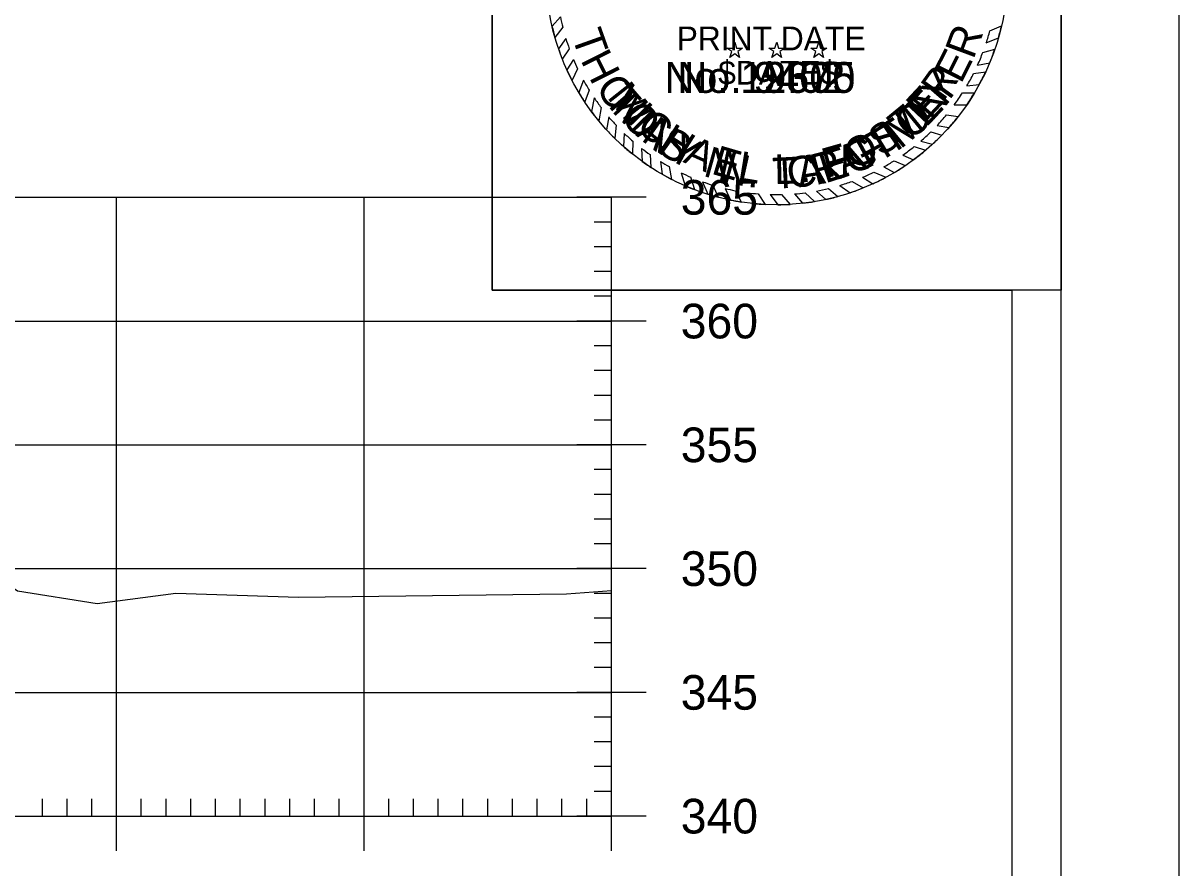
# Model space of a CAD drawing. Extents: x 1368910 to 1369601, y 380116 to 380950.
# Drawn here: x 1369553.81 to 1369600.52, y 380462.33 to 380496.46 of the extents above; entities that cross this region are included whole.
import ezdxf

# ---------------------------------------------------------------- set-up
doc = ezdxf.new("R2010")
doc.units = 0
for name, color, linetype in [('R_Axis', 7, 'Continuous'), ('R_Axis Annot', 7, 'Continuous'), ('R_Border', 7, 'Continuous'), ('R_Exist Surface', 7, 'Continuous'), ('R_Grid', 7, 'Continuous'), ('R_No Plot', 7, 'Continuous'), ('STAMP_PE_CRAFTON', 7, 'Continuous'), ('STAMP_PE_FOSTER', 7, 'Continuous'), ('STAMP_PE_SEAL-INFO', 7, 'Continuous'), ('STAMP_PE_TAEGTMEYER', 7, 'Continuous'), ('STAMP_PE_TXT', 7, 'Continuous'), ('STAMP_PRELIMINARY', 7, 'Continuous')]:
    doc.layers.add(name, color=color, linetype=linetype)

msp = doc.modelspace()

# ---------------------------------------------------------------- linework, layer by layer
at = {"layer": 'R_Axis'}
for p, q in [((1369578.99, 380489.421), (1369576.19, 380489.421)), ((1369577.59, 380464.421), (1369577.59, 380489.421)), ((1369577.59, 380488.421), (1369576.89, 380488.421)), ((1369577.59, 380487.421), (1369576.89, 380487.421)), ((1369577.59, 380486.421), (1369576.89, 380486.421)), ((1369577.59, 380485.421), (1369576.89, 380485.421)), ((1369578.99, 380484.421), (1369576.19, 380484.421)), ((1369577.59, 380483.421), (1369576.89, 380483.421)), ((1369577.59, 380482.421), (1369576.89, 380482.421)), ((1369577.59, 380481.421), (1369576.89, 380481.421)), ((1369577.59, 380480.421), (1369576.89, 380480.421)), ((1369578.99, 380479.421), (1369576.19, 380479.421)), ((1369577.59, 380478.421), (1369576.89, 380478.421)), ((1369577.59, 380477.421), (1369576.89, 380477.421)), ((1369577.59, 380476.421), (1369576.89, 380476.421)), ((1369577.59, 380475.421), (1369576.89, 380475.421)), ((1369578.99, 380474.421), (1369576.19, 380474.421)), ((1369577.59, 380473.421), (1369576.89, 380473.421)), ((1369577.59, 380472.421), (1369576.89, 380472.421)), ((1369577.59, 380471.421), (1369576.89, 380471.421)), ((1369577.59, 380470.421), (1369576.89, 380470.421)), ((1369578.99, 380469.421), (1369576.19, 380469.421)), ((1369577.59, 380468.421), (1369576.89, 380468.421)), ((1369577.59, 380467.421), (1369576.89, 380467.421)), ((1369577.59, 380466.421), (1369576.89, 380466.421)), ((1369557.59, 380463.021), (1369557.59, 380465.821)), ((1369567.59, 380463.021), (1369567.59, 380465.821)), ((1369577.59, 380463.021), (1369577.59, 380465.821)), ((1369577.59, 380465.421), (1369576.89, 380465.421)), ((1369554.59, 380464.421), (1369554.59, 380465.121)), ((1369555.59, 380464.421), (1369555.59, 380465.121)), ((1369556.59, 380464.421), (1369556.59, 380465.121)), ((1369558.59, 380464.421), (1369558.59, 380465.121)), ((1369559.59, 380464.421), (1369559.59, 380465.121)), ((1369560.59, 380464.421), (1369560.59, 380465.121)), ((1369561.59, 380464.421), (1369561.59, 380465.121)), ((1369562.59, 380464.421), (1369562.59, 380465.121)), ((1369563.59, 380464.421), (1369563.59, 380465.121)), ((1369564.59, 380464.421), (1369564.59, 380465.121)), ((1369565.59, 380464.421), (1369565.59, 380465.121)), ((1369566.59, 380464.421), (1369566.59, 380465.121)), ((1369568.59, 380464.421), (1369568.59, 380465.121)), ((1369569.59, 380464.421), (1369569.59, 380465.121)), ((1369570.59, 380464.421), (1369570.59, 380465.121)), ((1369571.59, 380464.421), (1369571.59, 380465.121)), ((1369572.59, 380464.421), (1369572.59, 380465.121)), ((1369573.59, 380464.421), (1369573.59, 380465.121)), ((1369574.59, 380464.421), (1369574.59, 380465.121)), ((1369575.59, 380464.421), (1369575.59, 380465.121)), ((1369576.59, 380464.421), (1369576.59, 380465.121)), ((1369297.59, 380464.421), (1369577.59, 380464.421)), ((1369578.99, 380464.421), (1369576.19, 380464.421))]:
    msp.add_line(p, q, dxfattribs=at)
at = {"layer": 'R_Border'}
msp.add_line((1369595.77, 380314.421), (1369595.77, 380519.881), dxfattribs=at)
at = {"layer": 'R_Exist Surface'}
msp.add_lwpolyline([(1369523.111, 380476.473), (1369549.701, 380476.252), (1369549.725, 380476.253), (1369549.738, 380476.255), (1369549.774, 380476.194), (1369553.587, 380473.527), (1369556.799, 380473.017), (1369559.991, 380473.431), (1369564.938, 380473.265), (1369575.777, 380473.406), (1369577.59, 380473.534)], dxfattribs=at)
at = {"layer": 'R_Grid'}
for p, q in [((1369297.59, 380489.421), (1369577.59, 380489.421)), ((1369557.59, 380464.421), (1369557.59, 380489.421)), ((1369567.59, 380464.421), (1369567.59, 380489.421)), ((1369577.59, 380464.421), (1369577.59, 380489.421)), ((1369297.59, 380484.421), (1369577.59, 380484.421)), ((1369297.59, 380479.421), (1369577.59, 380479.421)), ((1369297.59, 380474.421), (1369577.59, 380474.421)), ((1369297.59, 380469.421), (1369577.59, 380469.421)), ((1369297.59, 380464.421), (1369577.59, 380464.421))]:
    msp.add_line(p, q, dxfattribs=at)
at = {"layer": 'R_No Plot'}
for points in [[(1369267.182, 380523.775), (1369600.522, 380523.775), (1369600.522, 380310.438), (1369267.182, 380310.438)], [(1369593.77, 380419.151), (1369281.59, 380419.151), (1369281.59, 380517.881), (1369531.13, 380517.881), (1369531.13, 380508.001), (1369548.67, 380508.001), (1369572.77, 380508.001), (1369572.77, 380485.668), (1369593.77, 380485.668)], [(1369281.59, 380517.881), (1369531.13, 380517.881), (1369531.13, 380508.001), (1369548.67, 380508.001), (1369572.77, 380508.001), (1369572.77, 380485.668), (1369593.77, 380485.668), (1369593.77, 380316.421), (1369281.59, 380316.421)], [(1369572.77, 380510.001), (1369595.77, 380510.001), (1369595.77, 380485.668), (1369572.77, 380485.668)]]:
    msp.add_lwpolyline(points, close=True, dxfattribs=at)
at = {"layer": 'STAMP_PE_SEAL-INFO'}
for p, q in [((1369575.527, 380496.708), (1369575.188, 380496.34)), ((1369575.621, 380496.289), (1369575.308, 380495.874)), ((1369592.883, 380496.15), (1369593.355, 380496.352)), ((1369575.744, 380495.842), (1369575.45, 380495.424)), ((1369592.736, 380495.656), (1369593.227, 380495.857)), ((1369575.885, 380495.419), (1369575.604, 380495.007)), ((1369592.602, 380495.276), (1369593.084, 380495.407)), ((1369576.052, 380494.993), (1369575.79, 380494.57)), ((1369592.388, 380494.762), (1369592.876, 380494.858)), ((1369576.223, 380494.609), (1369575.996, 380494.148)), ((1369592.227, 380494.425), (1369592.715, 380494.494)), ((1369576.458, 380494.151), (1369576.267, 380493.661)), ((1369591.954, 380493.927), (1369592.455, 380493.981)), ((1369576.694, 380493.747), (1369576.51, 380493.276)), ((1369576.896, 380493.435), (1369576.787, 380492.883)), ((1369591.783, 380493.646), (1369592.26, 380493.64)), ((1369577.177, 380493.045), (1369577.075, 380492.514)), ((1369591.443, 380493.152), (1369591.948, 380493.155)), ((1369577.481, 380492.667), (1369577.394, 380492.147)), ((1369591.135, 380492.758), (1369591.597, 380492.679)), ((1369577.784, 380492.33), (1369577.722, 380491.808)), ((1369578.106, 380492.005), (1369578.076, 380491.475)), ((1369590.497, 380492.066), (1369590.938, 380491.928)), ((1369590.752, 380492.325), (1369591.229, 380492.24)), ((1369578.45, 380491.692), (1369578.447, 380491.163)), ((1369590.091, 380491.693), (1369590.563, 380491.565)), ((1369578.81, 380491.397), (1369578.829, 380490.873)), ((1369579.149, 380491.148), (1369579.185, 380490.63)), ((1369589.36, 380491.126), (1369589.799, 380490.937)), ((1369589.821, 380491.469), (1369590.288, 380491.324)), ((1369579.576, 380490.866), (1369579.637, 380490.354)), ((1369579.926, 380490.66), (1369580.017, 380490.147)), ((1369588.602, 380490.653), (1369589.019, 380490.421)), ((1369589.016, 380490.898), (1369589.466, 380490.703)), ((1369580.407, 380490.41), (1369580.564, 380489.889)), ((1369580.78, 380490.242), (1369580.953, 380489.731)), ((1369587.735, 380490.231), (1369588.158, 380489.97)), ((1369588.194, 380490.44), (1369588.678, 380490.228)), ((1369581.272, 380490.049), (1369581.482, 380489.547)), ((1369581.682, 380489.914), (1369581.908, 380489.425)), ((1369582.19, 380489.776), (1369582.402, 380489.31)), ((1369582.587, 380489.69), (1369582.834, 380489.232)), ((1369585.871, 380489.675), (1369586.259, 380489.335)), ((1369586.363, 380489.779), (1369586.741, 380489.454)), ((1369586.823, 380489.903), (1369587.239, 380489.606)), ((1369587.315, 380490.066), (1369587.758, 380489.798)), ((1369583.088, 380489.609), (1369583.328, 380489.168)), ((1369583.524, 380489.561), (1369583.798, 380489.133)), ((1369584.009, 380489.534), (1369584.311, 380489.121)), ((1369584.469, 380489.532), (1369584.812, 380489.136)), ((1369584.987, 380489.559), (1369585.313, 380489.179)), ((1369585.425, 380489.605), (1369585.798, 380489.247))]:
    msp.add_line(p, q, dxfattribs=at)
for radius, start, end in [(8.914, 191.2274, 193.9858), (9.323, 193.0369, 195.9973), (9.323, 343.8925, 347.035), (8.914, 196.9675, 199.8353), (8.914, 341.777, 345.0925), (9.323, 198.8967, 201.6281), (8.914, 335.6038, 339.1858), (9.323, 337.3837, 340.9933), (8.914, 202.7761, 205.4791), (9.323, 204.5479, 207.4328), (8.914, 329.5549, 333.2076), (9.323, 331.4037, 334.9332), (8.914, 208.7883, 211.7934), (9.323, 210.8636, 213.6571), (8.914, 214.1838, 217.2747), (8.914, 323.5851, 327.4407), (9.323, 325.4405, 328.9872), (9.323, 216.6115, 219.491), (8.914, 220.3909, 223.3056), (8.914, 316.6531, 320.3711), (9.323, 318.2846, 321.8043), (9.323, 222.48, 225.3801), (8.914, 226.2494, 229.2407), (8.914, 310.7744, 314.3161), (9.323, 312.4518, 315.6633), (9.323, 228.3665, 231.348), (8.914, 232.229, 234.9336), (8.914, 304.823, 308.5143), (9.323, 306.3721, 310.208), (9.323, 234.295, 236.9452), (8.914, 238.2223, 240.8353), (8.914, 299.0768, 302.1724), (9.323, 300.621, 303.8703), (9.323, 240.1977, 242.8613), (8.914, 244.3204, 246.9486), (8.914, 292.8745, 296.1185), (9.323, 294.6481, 298.2166), (9.323, 246.576, 249.1558), (8.914, 250.3491, 253.1216), (8.914, 256.505, 259.1192), (8.914, 280.3459, 283.5814), (8.914, 286.6423, 289.9783), (9.323, 288.5709, 291.9733), (9.323, 252.5967, 255.3252), (9.323, 258.4433, 261.1398), (8.914, 262.3783, 265.2012), (9.323, 264.1978, 267.1009), (8.914, 268.3215, 271.277), (8.914, 274.6157, 277.4486), (9.323, 276.4239, 279.4357), (9.323, 282.3199, 285.3702), (9.323, 270.2548, 273.3361)]:
    msp.add_arc((1369584.27, 380498.443), radius, start, end, dxfattribs=at)
at = {"layer": 'STAMP_PE_TXT'}
for p, q in [((1369582.449, 380495.308), (1369582.251, 380495.452)), ((1369582.251, 380495.452), (1369582.496, 380495.452)), ((1369582.374, 380495.075), (1369582.449, 380495.308)), ((1369582.496, 380495.452), (1369582.572, 380495.685)), ((1369582.572, 380495.685), (1369582.648, 380495.452)), ((1369582.648, 380495.452), (1369582.893, 380495.452)), ((1369582.893, 380495.452), (1369582.695, 380495.308)), ((1369582.695, 380495.308), (1369582.77, 380495.075)), ((1369584.147, 380495.308), (1369583.949, 380495.452)), ((1369583.949, 380495.452), (1369584.194, 380495.452)), ((1369584.072, 380495.075), (1369584.147, 380495.308)), ((1369584.194, 380495.452), (1369584.27, 380495.685)), ((1369584.27, 380495.685), (1369584.346, 380495.452)), ((1369584.346, 380495.452), (1369584.591, 380495.452)), ((1369584.591, 380495.452), (1369584.393, 380495.308)), ((1369584.393, 380495.308), (1369584.468, 380495.075)), ((1369585.845, 380495.308), (1369585.647, 380495.452)), ((1369585.647, 380495.452), (1369585.892, 380495.452)), ((1369585.77, 380495.075), (1369585.845, 380495.308)), ((1369585.892, 380495.452), (1369585.968, 380495.685)), ((1369585.968, 380495.685), (1369586.044, 380495.452)), ((1369586.044, 380495.452), (1369586.289, 380495.452)), ((1369586.289, 380495.452), (1369586.091, 380495.308)), ((1369586.091, 380495.308), (1369586.166, 380495.075)), ((1369582.572, 380495.219), (1369582.374, 380495.075)), ((1369582.77, 380495.075), (1369582.572, 380495.219)), ((1369584.27, 380495.219), (1369584.072, 380495.075)), ((1369584.468, 380495.075), (1369584.27, 380495.219)), ((1369585.968, 380495.219), (1369585.77, 380495.075)), ((1369586.166, 380495.075), (1369585.968, 380495.219))]:
    msp.add_line(p, q, dxfattribs=at)
at = {"layer": 'STAMP_PRELIMINARY'}
msp.add_circle((1369584.27, 380498.443), 9.323, dxfattribs=at)

# ---------------------------------------------------------------- texts
at = {"layer": 'R_Axis Annot'}
for s, p in [('365', (1369580.39, 380488.721)), ('360', (1369580.39, 380483.721)), ('355', (1369580.39, 380478.721)), ('350', (1369580.39, 380473.721)), ('345', (1369580.39, 380468.721)), ('340', (1369580.39, 380463.721))]:
    msp.add_text(s, height=1.4, dxfattribs=at).set_placement(p)
at = {"layer": 'STAMP_PE_CRAFTON'}
msp.add_text('No. 12370', height=1.25, dxfattribs=at).set_placement((1369579.732, 380493.64))
for s, rotation, p in [('T', 310.7442, (1369577.236, 380493.341)), ('N', 49.2411, (1369590.552, 380492.465)), ('O', 317.6422, (1369577.903, 380492.53)), ('O', 41.8391, (1369589.705, 380491.684)), ('N', 324.4537, (1369578.749, 380491.745)), ('T', 34.1136, (1369588.847, 380491.082)), ('Y', 331.1686, (1369579.782, 380491.029)), ('F', 28.7821, (1369587.931, 380490.573)), ('A', 20.5125, (1369586.951, 380490.199)), ('N', 347.4752, (1369581.837, 380490.113)), ('C', 6.0117, (1369584.741, 380489.785)), ('R', 14.8189, (1369585.838, 380489.899)), ('.', 356.8926, (1369583.066, 380489.836))]:
    msp.add_text(s, height=1.25, rotation=rotation, dxfattribs=at).set_placement(p)
at = {"layer": 'STAMP_PE_FOSTER'}
msp.add_text('No. 9402', height=1.25, dxfattribs=at).set_placement((1369580.256, 380493.64))
for s, rotation, p in [('R', 54.5031, (1369590.994, 380493.254)), ('M', 308.339, (1369577.386, 380493.465)), ('E', 46.9613, (1369590.271, 380492.433)), ('I', 314.1842, (1369578.184, 380492.528)), ('T', 39.4194, (1369589.412, 380491.683)), ('C', 319.8733, (1369578.538, 380492.175)), ('S', 31.7234, (1369588.461, 380491.056)), ('H', 327.7235, (1369579.467, 380491.438)), ('O', 23.719, (1369587.349, 380490.526)), ('A', 335.7276, (1369580.448, 380490.856)), ('E', 343.5779, (1369581.585, 380490.386)), ('F', 15.8691, (1369586.305, 380490.198)), ('L', 350.8115, (1369582.644, 380490.109)), ('L', 1.2666, (1369584.183, 380489.952)), ('.', 6.8035, (1369585.23, 380490.01))]:
    msp.add_text(s, height=1.2, rotation=rotation, dxfattribs=at).set_placement(p)
at = {"layer": 'STAMP_PE_TAEGTMEYER'}
for s, rotation, p in [('T', 289.646, (1369575.964, 380495.954)), ('R', 69.57, (1369592.215, 380494.958)), ('H', 296.7339, (1369576.324, 380494.969)), ('E', 63.0984, (1369591.716, 380493.976)), ('O', 303.7708, (1369576.917, 380493.861)), ('Y', 53.9986, (1369591.047, 380493.036)), ('M', 314.2033, (1369577.572, 380492.91)), ('E', 46.8094, (1369590.308, 380492.221)), ('M', 39.3, (1369589.268, 380491.342)), ('A', 321.0594, (1369578.534, 380491.945)), ('S', 327.8239, (1369579.36, 380491.301)), ('T', 31.466, (1369588.37, 380490.798)), ('G', 23.3052, (1369587.27, 380490.305)), ('N', 344.2727, (1369581.257, 380490.295)), ('T', 3.0061, (1369584.134, 380489.764)), ('A', 8.9826, (1369585.181, 380489.819)), ('E', 17.6836, (1369586.22, 380489.975)), ('.', 350.6464, (1369582.469, 380489.963))]:
    msp.add_text(s, height=1.25, rotation=rotation, dxfattribs=at).set_placement(p)
msp.add_text('No. 19605', height=1.25, dxfattribs=at).set_placement((1369579.732, 380493.64))
at = {"layer": 'STAMP_PRELIMINARY'}
for s, p in [('PRINT DATE', (1369580.227, 380495.359)), ('$DATE$', (1369581.904, 380493.974))]:
    msp.add_text(s, height=0.96, dxfattribs=at).set_placement(p)

doc.saveas('drawing.dxf')
